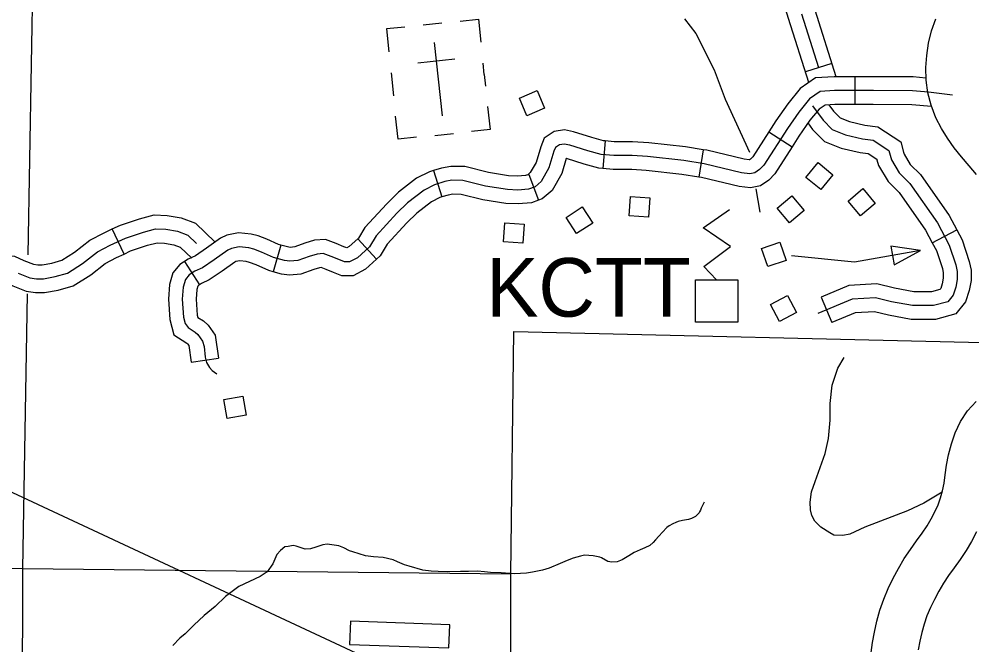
# Model space of a CAD drawing. Extents: x 1370130 to 1380143, y 377636 to 380256.
# Drawn here: x 1378335.4 to 1378551.8, y 378462.7 to 378605 of the extents above; entities that cross this region are included whole.
import ezdxf

# ---------------------------------------------------------------- set-up
doc = ezdxf.new("R2010")
doc.units = 0
for name, color, linetype in [('Level 10', 7, 'Continuous'), ('Level 32', 7, 'Continuous'), ('Level 34', 7, 'Continuous'), ('Level 35', 7, 'Continuous'), ('Level 45', 7, 'Continuous'), ('Level 5', 7, 'Continuous'), ('Level 56', 7, 'Continuous'), ('Level 57', 7, 'Continuous'), ('Level 6', 7, 'Continuous'), ('R_Draft', 7, 'Continuous')]:
    doc.layers.add(name, color=color, linetype=linetype)

msp = doc.modelspace()

# ---------------------------------------------------------------- linework, layer by layer
at = {"layer": 'Level 10'}
for p, q in [((1378542.64, 378602.3), (1378543.59, 378605.02)), ((1378541.95, 378599.5), (1378542.64, 378602.3)), ((1378541.54, 378596.72), (1378541.95, 378599.5)), ((1378541.36, 378593.94), (1378541.54, 378596.72)), ((1378541.42, 378591.11), (1378541.36, 378593.94)), ((1378541.8, 378588.21), (1378541.42, 378591.11)), ((1378542.52, 378585.4), (1378541.8, 378588.21)), ((1378543.56, 378582.51), (1378542.52, 378585.4)), ((1378544.9, 378580.11), (1378543.56, 378582.51)), ((1378546.24, 378577.92), (1378544.9, 378580.11)), ((1378547.79, 378575.67), (1378546.24, 378577.92)), ((1378549.44, 378573.62), (1378547.79, 378575.67)), ((1378551.13, 378571.59), (1378549.44, 378573.62)), ((1378552.87, 378569.61), (1378551.13, 378571.59)), ((1378550.82, 378515.95), (1378552.72, 378518.02)), ((1378549.2, 378513.54), (1378550.82, 378515.95)), ((1378547.98, 378510.94), (1378549.2, 378513.54)), ((1378547.12, 378508.41), (1378547.98, 378510.94)), ((1378546.48, 378505.94), (1378547.12, 378508.41)), ((1378546.05, 378503.56), (1378546.48, 378505.94)), ((1378545.75, 378501.39), (1378546.05, 378503.56)), ((1378545.47, 378499.47), (1378545.75, 378501.39)), ((1378545.13, 378497.75), (1378545.47, 378499.47)), ((1378544.69, 378496.15), (1378545.13, 378497.75)), ((1378543.39, 378492.97), (1378544.11, 378494.57)), ((1378544.11, 378494.57), (1378544.69, 378496.15)), ((1378542.57, 378491.39), (1378543.39, 378492.97)), ((1378541.61, 378489.81), (1378542.57, 378491.39)), ((1378539.22, 378486.36), (1378540.48, 378488.14)), ((1378540.48, 378488.14), (1378541.61, 378489.81)), ((1378552.85, 378488.4), (1378551.73, 378486.24)), ((1378537.84, 378484.44), (1378539.22, 378486.36)), ((1378551.73, 378486.24), (1378550.46, 378484.15)), ((1378536.44, 378482.33), (1378537.84, 378484.44)), ((1378550.46, 378484.15), (1378549.12, 378482.16)), ((1378535.15, 378480.13), (1378536.44, 378482.33)), ((1378549.12, 378482.16), (1378547.77, 378480.26)), ((1378533.94, 378477.9), (1378535.15, 378480.13)), ((1378547.77, 378480.26), (1378546.49, 378478.48)), ((1378532.79, 378475.56), (1378533.94, 378477.9)), ((1378546.49, 378478.48), (1378545.35, 378476.76)), ((1378531.76, 378473.11), (1378532.79, 378475.56)), ((1378544.29, 378474.96), (1378543.27, 378473.08)), ((1378545.35, 378476.76), (1378544.29, 378474.96)), ((1378530.88, 378470.61), (1378531.76, 378473.11)), ((1378543.27, 378473.08), (1378542.35, 378471.21)), ((1378530.19, 378468.1), (1378530.88, 378470.61)), ((1378542.35, 378471.21), (1378541.56, 378469.33)), ((1378541.56, 378469.33), (1378540.91, 378467.47)), ((1378529.64, 378465.63), (1378530.19, 378468.1)), ((1378540.91, 378467.47), (1378540.38, 378465.57)), ((1378529.23, 378463.26), (1378529.64, 378465.63)), ((1378540.38, 378465.57), (1378539.95, 378463.6)), ((1378528.91, 378460.99), (1378529.23, 378463.26)), ((1378539.95, 378463.6), (1378539.6, 378461.61))]:
    msp.add_line(p, q, dxfattribs=at)
at = {"layer": 'Level 32'}
for p, q in [((1378525.23, 378591.87), (1378525.23, 378585.57)), ((1378505.67, 378579.34), (1378510.96, 378575.91)), ((1378468.47, 378577.26), (1378467.96, 378570.98)), ((1378490.78, 378575.27), (1378489.78, 378569.05)), ((1378429.53, 378570.54), (1378431.42, 378564.53)), ((1378451.14, 378569.67), (1378453.35, 378563.77)), ((1378412.3, 378555.03), (1378416.56, 378550.39)), ((1378394.82, 378553.6), (1378393.1, 378547.54)), ((1378372.95, 378549.87), (1378376.35, 378544.57))]:
    msp.add_line(p, q, dxfattribs=at)
for points in [[(1378525.23, 378591.87), (1378520.47, 378591.87), (1378516.27, 378591.6), (1378512.78, 378589.17), (1378509.95, 378585.73), (1378507.27, 378581.81), (1378505.67, 378579.34)], [(1378541.36, 378591.56), (1378538.48, 378591.81), (1378529.42, 378591.87), (1378525.23, 378591.87)], [(1378547.35, 378587.69), (1378541.93, 378588.35), (1378538.33, 378588.66), (1378529.41, 378588.72), (1378520.57, 378588.72), (1378517.35, 378588.52), (1378514.94, 378586.83), (1378512.47, 378583.84), (1378509.9, 378580.06), (1378504.51, 378571.75), (1378503.58, 378570.75), (1378502.51, 378570.03), (1378501.36, 378569.8), (1378499.47, 378570.03), (1378490.96, 378572.05), (1378486.36, 378572.79), (1378478.12, 378573.71), (1378474.62, 378573.94), (1378470.44, 378573.94), (1378467.58, 378574.17), (1378464.59, 378575), (1378460.5, 378576.29), (1378459.21, 378576.57), (1378458.1, 378576.38), (1378457.22, 378575.8), (1378456.86, 378574.91), (1378455.71, 378571.13), (1378453.96, 378568.05), (1378452.58, 378566.85), (1378451.11, 378566.3), (1378448.67, 378566.11), (1378446.28, 378566.21), (1378441.35, 378566.99), (1378436.2, 378568.28), (1378433.67, 378568.32), (1378432.1, 378568.05), (1378429.75, 378567.31), (1378427.36, 378566.11), (1378423.63, 378563.21), (1378421.19, 378560.82), (1378416.47, 378555.68), (1378414.94, 378553.17), (1378412.22, 378550.69), (1378410.47, 378549.77), (1378409.32, 378549.77), (1378407.98, 378550.31), (1378406.28, 378551), (1378404.49, 378551.65), (1378403.06, 378551.56), (1378401.31, 378551.01), (1378398.69, 378550.09), (1378396.9, 378549.91), (1378395.65, 378550.09), (1378393.21, 378550.78), (1378390.45, 378552.02), (1378388.7, 378552.67), (1378387.55, 378552.99), (1378385.34, 378553.17), (1378383.6, 378552.85), (1378382.77, 378552.44), (1378379.73, 378550.27), (1378377.02, 378548.43), (1378375.31, 378547.65), (1378374.02, 378546.82), (1378373.15, 378545.76), (1378372.64, 378544.06), (1378372.46, 378541.29), (1378372.74, 378537.2), (1378373.1, 378535.77), (1378373.76, 378534.86), (1378375.36, 378533.84), (1378376, 378533.28), (1378377.06, 378531.76), (1378377.43, 378530.52), (1378377.66, 378528.13), (1378377.94, 378526.93), (1378378.67, 378525.78), (1378379.22, 378525.09), (1378380.28, 378524.35)], [(1378525.23, 378585.57), (1378520.67, 378585.57), (1378518.43, 378585.43), (1378517.1, 378584.49), (1378515, 378581.95), (1378512.52, 378578.32), (1378510.96, 378575.91)], [(1378542.62, 378585.13), (1378538.18, 378585.51), (1378529.4, 378585.57), (1378525.23, 378585.57)], [(1378468.47, 378577.26), (1378468.13, 378577.29), (1378465.48, 378578.02), (1378461.3, 378579.34), (1378459.28, 378579.77), (1378456.93, 378579.38), (1378454.66, 378577.9), (1378453.89, 378575.95), (1378452.8, 378572.38), (1378451.49, 378570.07), (1378450.94, 378569.6), (1378451.14, 378569.67)], [(1378505.67, 378579.34), (1378502.01, 378573.69), (1378501.51, 378573.16), (1378501.27, 378572.99), (1378501.24, 378572.98), (1378500.03, 378573.13), (1378491.57, 378575.14), (1378490.78, 378575.27)], [(1378490.78, 378575.27), (1378486.78, 378575.91), (1378478.4, 378576.85), (1378474.73, 378577.09), (1378470.56, 378577.09), (1378468.47, 378577.26)], [(1378510.96, 378575.91), (1378507, 378569.81), (1378505.64, 378568.35), (1378503.75, 378567.06), (1378501.48, 378566.61), (1378498.92, 378566.92), (1378490.35, 378568.96), (1378489.78, 378569.05)], [(1378467.96, 378570.98), (1378467.03, 378571.06), (1378463.7, 378571.98), (1378459.69, 378573.24), (1378459.65, 378573.25), (1378458.62, 378569.88), (1378456.43, 378566.02), (1378454.22, 378564.1), (1378453.35, 378563.77)], [(1378429.53, 378570.54), (1378428.57, 378570.24), (1378425.67, 378568.79), (1378421.56, 378565.59), (1378418.93, 378563.01), (1378413.94, 378557.58), (1378412.48, 378555.2), (1378412.3, 378555.03)], [(1378451.14, 378569.67), (1378450.42, 378569.4), (1378448.61, 378569.27), (1378446.58, 378569.35), (1378441.98, 378570.08), (1378436.61, 378571.42), (1378433.42, 378571.48), (1378431.35, 378571.11), (1378429.53, 378570.54)], [(1378489.78, 378569.05), (1378485.93, 378569.67), (1378477.84, 378570.57), (1378474.52, 378570.79), (1378470.31, 378570.79), (1378467.96, 378570.98)], [(1378431.42, 378564.53), (1378430.94, 378564.38), (1378429.05, 378563.44), (1378425.71, 378560.84), (1378423.46, 378558.63), (1378418.99, 378553.77), (1378417.39, 378551.15), (1378416.56, 378550.39)], [(1378453.35, 378563.77), (1378451.79, 378563.19), (1378448.73, 378562.96), (1378445.97, 378563.06), (1378440.72, 378563.9), (1378435.78, 378565.13), (1378433.91, 378565.17), (1378432.85, 378564.98), (1378431.42, 378564.53)], [(1378394.82, 378553.6), (1378394.3, 378553.75), (1378391.65, 378554.94), (1378389.68, 378555.67), (1378388.11, 378556.1), (1378385.19, 378556.35), (1378382.59, 378555.87), (1378381.14, 378555.15), (1378377.93, 378552.86), (1378375.46, 378551.18), (1378373.8, 378550.42), (1378371.91, 378549.2)], [(1378412.3, 378555.03), (1378410.39, 378553.29), (1378409.8, 378552.97), (1378409.16, 378553.23), (1378407.41, 378553.94), (1378404.95, 378554.84), (1378402.48, 378554.68), (1378400.32, 378554), (1378398, 378553.18), (1378396.97, 378553.08), (1378396.32, 378553.18), (1378394.82, 378553.6)], [(1378371.91, 378549.2), (1378370.31, 378547.27), (1378369.52, 378544.62), (1378369.3, 378541.29), (1378369.61, 378536.69), (1378370.51, 378533.21), (1378373.47, 378531.3), (1378373.65, 378531.15), (1378373.92, 378530.76), (1378374.47, 378526.98), (1378380.71, 378527.89)], [(1378393.1, 378547.54), (1378392.13, 378547.81), (1378389.26, 378549.11), (1378387.73, 378549.67), (1378386.99, 378549.88), (1378385.5, 378550), (1378384.61, 378549.84), (1378384.4, 378549.73), (1378381.53, 378547.69), (1378378.57, 378545.68), (1378376.83, 378544.88), (1378376.14, 378544.44)], [(1378416.56, 378550.39), (1378414.05, 378548.09), (1378411.25, 378546.62), (1378408.71, 378546.62), (1378406.8, 378547.39), (1378405.14, 378548.06), (1378404.03, 378548.47), (1378403.65, 378548.44), (1378402.31, 378548.02), (1378399.38, 378546.99), (1378396.82, 378546.73), (1378394.99, 378547), (1378393.1, 378547.54)], [(1378376.14, 378544.44), (1378375.99, 378544.25), (1378375.76, 378543.5), (1378375.62, 378541.3), (1378375.86, 378537.7), (1378375.99, 378537.17), (1378377.25, 378536.37), (1378378.36, 378535.41), (1378379.94, 378533.15), (1378380.71, 378527.89)]]:
    msp.add_lwpolyline(points, dxfattribs=at)
at = {"layer": 'Level 34'}
msp.add_lwpolyline([(1378545.07, 378497.44), (1378540.9, 378494.94), (1378537.17, 378493.23), (1378527.49, 378489.51), (1378524.08, 378487.91), (1378522.49, 378487.59), (1378520.46, 378487.7), (1378519.51, 378488.23), (1378517.48, 378489.51), (1378516.1, 378490.89), (1378515.46, 378492.17), (1378515.14, 378493.45), (1378515.04, 378495.15), (1378515.36, 378497.49), (1378516.21, 378499.84), (1378518.44, 378506.23), (1378519.19, 378509.63), (1378519.61, 378513.79), (1378519.61, 378517.62), (1378520.04, 378521.77), (1378521.32, 378525.61), (1378522.81, 378528.06)], dxfattribs=at)
at = {"layer": 'Level 35'}
for points in [[(1378486.49, 378604.98), (1378489.12, 378601.71), (1378493.28, 378593.45), (1378495.74, 378586.77), (1378501.27, 378574.75)], [(1378502.75, 378566.38), (1378503.59, 378561.1)], [(1378490.98, 378495.18), (1378490.51, 378494.24), (1378490.27, 378493.77), (1378490.16, 378493.35), (1378489.92, 378492.97), (1378489.88, 378492.75), (1378488.98, 378491.93), (1378488.07, 378491.48), (1378487.41, 378491.25), (1378486.03, 378491), (1378485.08, 378490.8), (1378484.58, 378490.58), (1378483.83, 378490.26), (1378483.05, 378489.77), (1378482.47, 378489.38), (1378481.5, 378488.38), (1378480.69, 378487.43), (1378479.96, 378486.61), (1378479.43, 378486.01), (1378478.65, 378485.31), (1378477.49, 378484.77), (1378476.42, 378484.36), (1378475.09, 378483.73), (1378473.86, 378482.98), (1378472.33, 378482.05), (1378471.25, 378481.64), (1378470.04, 378481.52), (1378469.11, 378481.7), (1378467.66, 378482.54), (1378467.28, 378482.66), (1378465.76, 378482.99), (1378463.79, 378483.1), (1378462.91, 378482.9), (1378461.25, 378482.47), (1378459.84, 378481.93), (1378458.27, 378481.21), (1378455.78, 378480.17), (1378454.24, 378479.7), (1378452.03, 378479.25), (1378450.61, 378479.04), (1378447.93, 378478.92), (1378444.87, 378479.12), (1378442.43, 378479.18), (1378441.09, 378479.31), (1378439.49, 378479.47), (1378437.48, 378479.45), (1378435.63, 378479.39), (1378432.66, 378479.35), (1378430.6, 378479.41), (1378429, 378479.49), (1378427.07, 378479.73), (1378423.98, 378480.64), (1378422.92, 378480.95), (1378421.35, 378481.62), (1378420.33, 378482.05), (1378418.05, 378482.57), (1378415.91, 378482.76), (1378414.1, 378483), (1378411.18, 378483.92), (1378410.46, 378484.11), (1378409.14, 378484.78), (1378408.03, 378485.25), (1378406.43, 378485.5), (1378405.38, 378485.59), (1378404.38, 378485.44), (1378402.8, 378484.97), (1378401.59, 378484.6), (1378400.38, 378484.52), (1378398.35, 378485.17), (1378397.67, 378485.36), (1378396.51, 378485.08), (1378395.71, 378485.01), (1378394.77, 378484.22), (1378393.92, 378483.27), (1378393.01, 378481.14), (1378391.77, 378479.34), (1378390.12, 378478.28), (1378385.28, 378476.03), (1378382.24, 378473.76), (1378379.92, 378471.46), (1378377.46, 378469.45), (1378375.1, 378467.19), (1378373.1, 378465.28), (1378371.91, 378464.28), (1378370.29, 378462.59)]]:
    msp.add_lwpolyline(points, dxfattribs=at)
at = {"layer": 'Level 45'}
for p, q in [((1378520, 378594.86), (1378514, 378592.96)), ((1378359.23, 378551.57), (1378356.57, 378557.28)), ((1378542.79, 378554.12), (1378548.36, 378557.07)), ((1378517.53, 378541.77), (1378519.99, 378535.97))]:
    msp.add_line(p, q, dxfattribs=at)
for points in [[(1378520.95, 378591.87), (1378516.16, 378606.99), (1378513.76, 378614.78), (1378512.75, 378616.51)], [(1378514.76, 378590.55), (1378510.15, 378605.11), (1378507.95, 378612.23), (1378507.31, 378613.33)], [(1378517, 378593.91), (1378513.15, 378606.05)], [(1378519.31, 378585.48), (1378520.39, 378584), (1378521.85, 378582.54), (1378524.01, 378581.67), (1378527.5, 378580.87), (1378530.46, 378580.5), (1378535.63, 378577.05), (1378536.29, 378574.74)], [(1378515.6, 378585.23), (1378517.99, 378581.95), (1378520.08, 378579.85), (1378523.06, 378578.66), (1378526.94, 378577.76), (1378529.33, 378577.47), (1378532.91, 378575.08), (1378533.51, 378572.99), (1378535.3, 378570), (1378537.69, 378567.61), (1378543.96, 378558.65), (1378546.65, 378553.57), (1378548.14, 378549.09), (1378548.44, 378547.6), (1378548.44, 378545.81), (1378548.14, 378544.01), (1378547.54, 378542.22), (1378546.35, 378540.73), (1378543.06, 378539.83), (1378538.29, 378539.83), (1378533.51, 378540.73), (1378529.93, 378541.62), (1378524.56, 378541.33), (1378516.8, 378538.04)], [(1378514.52, 378581.37), (1378515.59, 378579.89), (1378518.31, 378577.17), (1378522.12, 378575.65), (1378526.39, 378574.66), (1378528.2, 378574.43), (1378530.2, 378573.1), (1378530.23, 378573.01)], [(1378536.29, 378574.74), (1378536.43, 378574.25), (1378537.8, 378571.95), (1378540.11, 378569.64), (1378546.65, 378560.29), (1378548.36, 378557.07)], [(1378530.23, 378573.01), (1378530.6, 378571.72), (1378532.8, 378568.05), (1378535.27, 378565.58), (1378541.27, 378557), (1378542.79, 378554.12)], [(1378356.57, 378557.28), (1378358.39, 378558.13), (1378362.76, 378559.58), (1378366.04, 378560.45), (1378369.06, 378560.35), (1378372.22, 378559.77), (1378375.43, 378558.56), (1378379.89, 378554.25)], [(1378335.2, 378547.23), (1378337.85, 378546.19), (1378339.38, 378545.95), (1378340.91, 378545.95), (1378343.56, 378546.43), (1378346.37, 378547.23), (1378349.83, 378549.41), (1378353.21, 378552.06), (1378356.1, 378553.59), (1378359.56, 378555.2), (1378363.66, 378556.57), (1378366.39, 378557.29), (1378368.72, 378557.21), (1378371.38, 378556.73), (1378373.71, 378555.84), (1378375.66, 378553.96)], [(1378338.68, 378549.25), (1378339.63, 378549.1), (1378340.62, 378549.1), (1378342.84, 378549.5), (1378345.08, 378550.14), (1378348.01, 378551.98), (1378351.48, 378554.71), (1378354.7, 378556.41), (1378356.57, 378557.28)], [(1378548.36, 378557.07), (1378549.55, 378554.81), (1378551.19, 378549.9), (1378551.59, 378547.91), (1378551.59, 378545.55), (1378551.2, 378543.25), (1378550.35, 378540.69), (1378548.17, 378537.96), (1378543.49, 378536.68), (1378540.24, 378536.68)], [(1378359.23, 378551.57), (1378360.73, 378552.27), (1378364.56, 378553.55), (1378366.75, 378554.12), (1378368.39, 378554.07), (1378370.53, 378553.68), (1378371.99, 378553.13), (1378374.6, 378550.6)], [(1378542.79, 378554.12), (1378543.74, 378552.33), (1378545.09, 378548.28), (1378545.29, 378547.29), (1378545.29, 378546.07), (1378545.07, 378544.78), (1378544.73, 378543.75), (1378544.53, 378543.5), (1378542.64, 378542.98), (1378540.24, 378542.98)], [(1378317.05, 378545.32), (1378317.68, 378545.46), (1378320.72, 378547.08), (1378322.86, 378548.69), (1378325.56, 378550.46), (1378329.41, 378551.17), (1378332.03, 378551.36), (1378334.38, 378551.11), (1378336.45, 378550.12), (1378338.68, 378549.25)], [(1378337.52, 378543.05), (1378339.13, 378542.8), (1378341.19, 378542.8), (1378344.28, 378543.36), (1378347.67, 378544.33), (1378351.65, 378546.83), (1378354.93, 378549.41), (1378357.5, 378550.77), (1378359.23, 378551.57)], [(1378318.47, 378539.18), (1378319.91, 378539.51), (1378324.11, 378541.75), (1378326.47, 378543.53), (1378327.95, 378544.49), (1378330.21, 378544.91), (1378331.93, 378545.04), (1378332.64, 378544.96), (1378333.94, 378544.34), (1378337.02, 378543.13), (1378337.52, 378543.05)], [(1378540.24, 378542.98), (1378538.58, 378542.98), (1378534.18, 378543.81), (1378530.23, 378544.8), (1378523.83, 378544.44), (1378517.53, 378541.77)], [(1378540.24, 378536.68), (1378537.99, 378536.68), (1378532.84, 378537.65), (1378529.63, 378538.45), (1378525.28, 378538.21), (1378519.99, 378535.97)]]:
    msp.add_lwpolyline(points, dxfattribs=at)
at = {"layer": 'Level 5'}
for points in [[(1378340.06, 378703.15), (1378337.41, 378551.4)], [(1378337.26, 378542.52), (1378336.17, 378480.01)], [(1378336.17, 378480.01), (1378239.5, 378482.59)], [(1378336.17, 378480.01), (1378335.75, 378291.72)], [(1378447.06, 378478.81), (1378336.17, 378480.01)]]:
    msp.add_lwpolyline(points, dxfattribs=at)
at = {"layer": 'Level 56'}
for points in [[(1378449.01, 378587.01), (1378453.03, 378588.71), (1378454.74, 378584.68), (1378450.71, 378582.97)], [(1378514.07, 378568.99), (1378516.85, 378572.36), (1378520.24, 378569.57), (1378517.46, 378566.2)], [(1378529.85, 378563.08), (1378526.52, 378560.25), (1378523.68, 378563.59), (1378527.01, 378566.42)], [(1378473.94, 378560.28), (1378474.26, 378564.64), (1378478.63, 378564.32), (1378478.32, 378559.96)], [(1378507.56, 378562.01), (1378510.91, 378564.82), (1378513.72, 378561.46), (1378510.37, 378558.65)], [(1378461.97, 378556.21), (1378459.62, 378559.9), (1378463.31, 378562.26), (1378465.67, 378558.58)], [(1378445.41, 378554.31), (1378445.72, 378558.67), (1378450.1, 378558.36), (1378449.78, 378554)], [(1378504.03, 378552.85), (1378508.16, 378554.26), (1378509.58, 378550.11), (1378505.45, 378548.7)], [(1378533.37, 378553.35), (1378534.13, 378549.13), (1378540.08, 378552.38)], [(1378506.06, 378540.11), (1378509.92, 378542.16), (1378511.97, 378538.28), (1378508.11, 378536.24)], [(1378386.93, 378514.91), (1378382.62, 378514.16), (1378381.87, 378518.48), (1378386.18, 378519.23)]]:
    msp.add_lwpolyline(points, close=True, dxfattribs=at)
msp.add_lwpolyline([(1378540.08, 378552.38), (1378525.15, 378549.69), (1378510.83, 378551.18)], dxfattribs=at)
at = {"layer": 'Level 57'}
for p, q in [((1378431.38, 378604.05), (1378427.2, 378603.61)), ((1378429.7, 378599.65), (1378431.46, 378582.94)), ((1378425.97, 378595.03), (1378434.36, 378595.91)), ((1378441.03, 378592.39), (1378440.76, 378594.97)), ((1378419.87, 378592.77), (1378420.42, 378587.54)), ((1378441.03, 378592.39), (1378441.31, 378589.74)), ((1378430.58, 378591.29), (1378430.58, 378591.29)), ((1378430.58, 378591.29), (1378430.58, 378591.29)), ((1378429.84, 378578.54), (1378434.02, 378578.98)), ((1378410.65, 378468.1), (1378410.46, 378462.86)), ((1378433.21, 378467.28), (1378410.65, 378468.1)), ((1378433.02, 378462.03), (1378433.21, 378467.28)), ((1378410.46, 378462.86), (1378433.02, 378462.03))]:
    msp.add_line(p, q, dxfattribs=at)
for points in [[(1378435.53, 378604.48), (1378439.71, 378604.92), (1378440.26, 378599.7)], [(1378423, 378603.16), (1378418.82, 378602.72), (1378419.37, 378597.5)], [(1378441.8, 378585.08), (1378442.35, 378579.86), (1378438.17, 378579.42)], [(1378425.64, 378578.1), (1378421.46, 378577.66), (1378420.91, 378582.88)], [(1378493.82, 378545.72), (1378490.94, 378548.71), (1378496.98, 378553.24), (1378490.77, 378557.5), (1378496.71, 378561.67)]]:
    msp.add_lwpolyline(points, dxfattribs=at)
msp.add_lwpolyline([(1378489, 378536.08), (1378489, 378545.72), (1378498.64, 378545.72), (1378498.64, 378536.08)], close=True, dxfattribs=at)
at = {"layer": 'Level 6'}
msp.add_lwpolyline([(1378447, 378338.17), (1378447.06, 378478.81), (1378447.73, 378533.93), (1378557.43, 378531.41), (1378566.41, 378531.19)], dxfattribs=at)
at = {"layer": 'R_Draft'}
msp.add_line((1378016.31, 378645.48), (1378559.62, 378392.03), dxfattribs=at)

# ---------------------------------------------------------------- texts
at = {"layer": 'Level 57'}
msp.add_text('KCTT', height=13.306, dxfattribs=at).set_placement((1378441.47, 378537.34))

doc.saveas('drawing.dxf')
